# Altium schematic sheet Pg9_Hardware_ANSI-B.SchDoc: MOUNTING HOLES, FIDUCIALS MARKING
size 431 x 279 mm; Date: Not shown in title block; ApprovedBy: Not shown in title block; CheckedBy: Not shown in title block; Author: Not shown in title block; CompanyName: Not shown in title block; Engineer: Not shown in title block; Organization: Not shown in title block; Address1: Not shown in title block; Address2: Not shown in title block; Address3: Not shown in title block; Address4: Not shown in title block; DocumentNumber: 9; Revision: Use project parameter SCH_Rev; SheetNumber: 9; SheetTotal: 9; PageSetup: Record=PageOptions|CenterHorizontal=True|CenterVertical=True|PrintScale=1.00|XCorrection=1.00|YCorrection=1.00|PrintKind=0|BorderSize=5000000|LeftOffset=0|BottomOffset=0|Orientation=2|PaperLength=1000|PaperWidth=1000|Scale=100|PaperSource=15|PrintQuality=600|MediaType=1|DitherType=10|PaperKind=Letter|PrintScaleMode=1
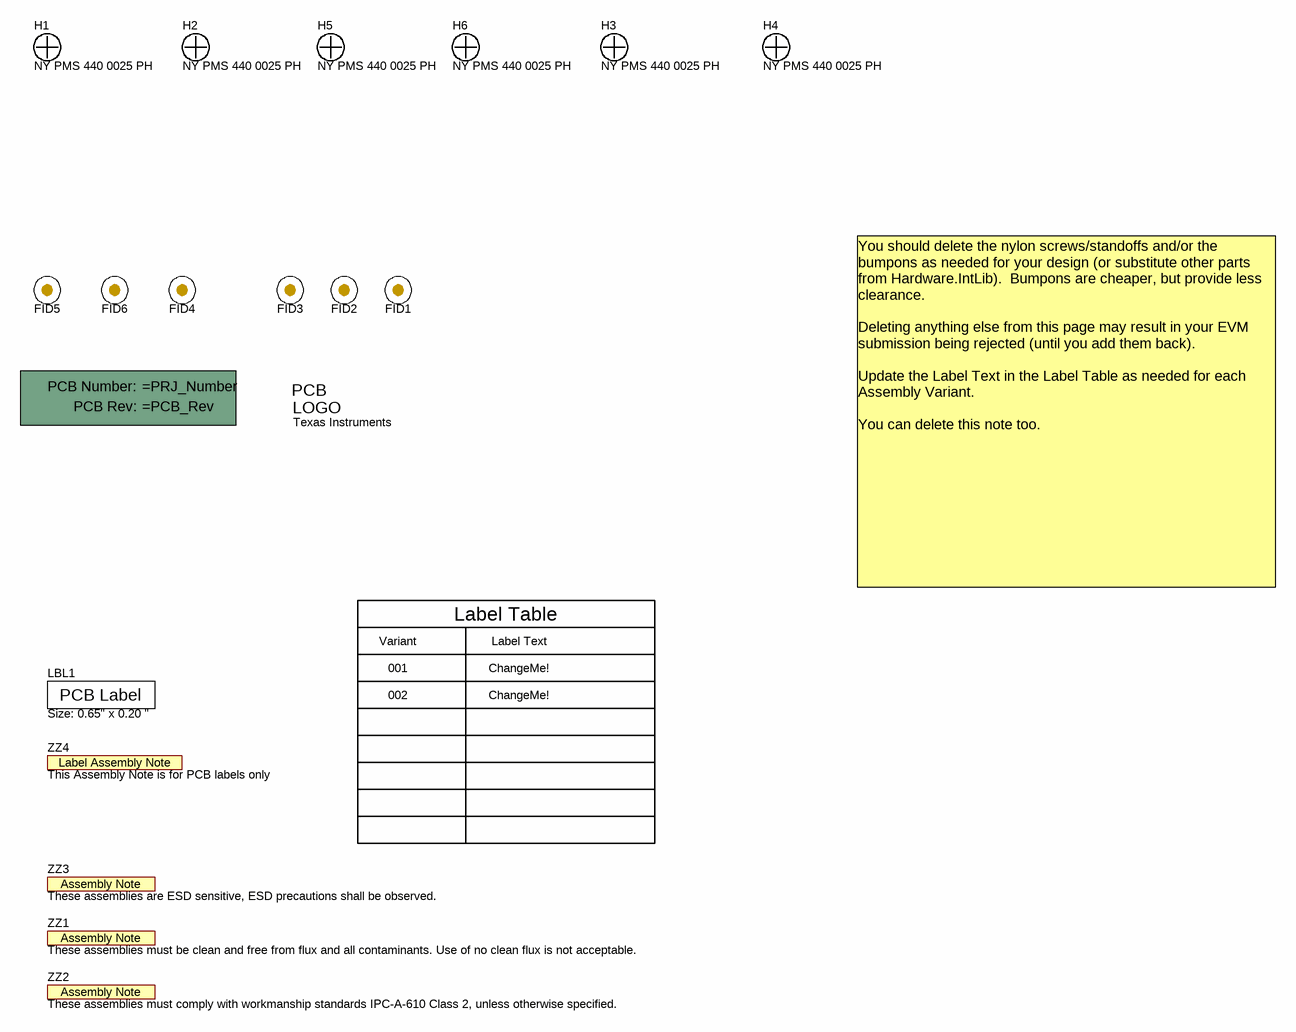
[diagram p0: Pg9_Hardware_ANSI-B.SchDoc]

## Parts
!PCB  Printed Circuit Board  (value not drawn)  (mechanical)
FID1  Fiducial  [Fiducial10-20]  (value not drawn)
FID2  Fiducial  [Fiducial10-20]  (value not drawn)
FID3  Fiducial  [Fiducial10-20]  (value not drawn)
FID4  Fiducial  [Fiducial10-20]  (value not drawn)
FID5  Fiducial  [Fiducial10-20]  (value not drawn)
FID6  Fiducial  [Fiducial10-20]  (value not drawn)
H1  NY PMS 440 0025 PH  [MH3.2_H5_W6_KO8_STARHEAD]
H2  NY PMS 440 0025 PH  [MH3.2_H5_W6_KO8_STARHEAD]
H3  NY PMS 440 0025 PH  [MH3.2_H5_W6_KO8_STARHEAD]
H4  NY PMS 440 0025 PH  [MH3.2_H5_W6_KO8_STARHEAD]
H5  NY PMS 440 0025 PH  [MH3.2_H5_W6_KO8_STARHEAD]
H6  NY PMS 440 0025 PH  [MH3.2_H5_W6_KO8_STARHEAD]
LBL1  Size: 0.65" x 0.20 "  [Label_650x200]
Logo1  Texas Instruments  [TI_Stacked_SolderMask_Small]  (no BOM)
ZZ1  These assemblies must be clean and free from flux and all contaminants. Use of no clean flux is not acceptable.  [AssemblyNote]  (no BOM)
ZZ2  These assemblies must comply with workmanship standards IPC-A-610 Class 2, unless otherwise specified.  [AssemblyNote]  (no BOM)
ZZ3  These assemblies are ESD sensitive, ESD precautions shall be observed.  [AssemblyNote]  (no BOM)
ZZ4  This Assembly Note is for PCB labels only  [AssemblyNoteLabel]  (no BOM)

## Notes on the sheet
- Variant
- Label Table
- Label Text
- You should delete the nylon screws/standoffs and/or the bumpons as needed for your design (or substitute other parts from Hardware.IntLib).  Bumpons are cheaper, but provide less clearance.
  Deleting anything else from this page may result in your EVM submission being rejected (until you add them back).
  Update the Label Text in the Label Table as needed for each Assembly Variant.
  You can delete this note too.
- 001
- 002
- ChangeMe!

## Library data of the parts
!PCB = PCB: Manufacturer: Any; SymbolCreator: a0412235
FID1-FID6 = Fiducial: Fiducial mark.  There is nothing to buy or mount.; SymbolCreator: codlsc
H1-H6 = NY PMS 440 0025 PH: Machine Screw, Round, #4-40 x 1/4, Nylon, Philips panhead; Manufacturer: B&F Fastener Supply; CompType: Hardware; SymbolCreator: codlsc; U/M: EA
LBL1 = THT-14-423-10: Thermal Transfer Printable Labels, 0.650" W x 0.200" H - 10,000 per roll; Manufacturer: Brady; SymbolCreator: a0412235; CompType: Label
Logo1 = TI_Logo: Texas Instrument Corporate Signature; SymbolCreator: codlsc
ZZ1-ZZ3 = AssemblyNote: SymbolCreator: codlsc
ZZ4 = AssemblyNoteLabel: SymbolCreator: a0412235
